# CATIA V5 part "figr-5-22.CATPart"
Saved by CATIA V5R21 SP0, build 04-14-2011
Part number: Part1
Bounding box of the stored display mesh (mm): x -50 to 50, y 0 to 90.129, z 0 to 181.346
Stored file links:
  D:\CATIA V5R21 E-RESOURCES\CATIA-V5R21\catia-v5r21-prt\c05-catia-v5r20-prt\catia-v5r21-figr-5-22.CATPart
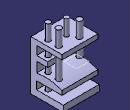
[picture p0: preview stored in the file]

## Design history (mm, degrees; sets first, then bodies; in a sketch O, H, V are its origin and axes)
Set1
  Plane1: type Offset, RefPlane face of Pad1, Offset 44, reversed
  Plane2: type Offset, RefPlane face of Pad1, Offset -46, reversed
Body1 (main body)
  Sketch1 on yz-plane, origin (0, 0, 0), H (0, 1, 0), V (0, 0, 1)
    line L1 (0, 0) -> (90.1292, 0)
    line L2 (90.1292, 0) -> (90.1292, 17.5473)
    line L3 (90.1292, 17.5473) -> (15.9521, 17.5473)
    line L4 (15.9521, 17.5473) -> (15.9521, 39.2532)
    line L5 (15.9521, 39.2532) -> (86.4281, 39.2532)
    line L6 (86.4281, 39.2532) -> (86.4281, 51.1017)
    arc A1 centre (39.4717, -66.63) radius 126.7503 from (86.4281, 51.1017) to (16.1896, 57.9637) ccw
    line L7 (16.1896, 57.9637) -> (16.1896, 86.2043)
    line L8 (16.1896, 86.2043) -> (46.6673, 86.2043)
    line L9 (46.6673, 86.2043) -> (46.6673, 100.2494)
    line L10 (46.6673, 100.2494) -> (16.1896, 100.2494)
    point P12 (16.1896, 100.2494)
    line L11 (16.1896, 100.2494) -> (16.1896, 124.3269)
    line L12 (16.1896, 124.3269) -> (86.4281, 124.3269)
    point P14 (86.4281, 124.3269)
    line L13 (86.4281, 124.3269) -> (86.4281, 137.3459)
    line L14 (86.4281, 137.3459) -> (0, 137.3459)
    point P16 (0, 137.3459)
    line L15 (0, 137.3459) -> (0, 0)
    horizontal: L1 H, L3 H, L5 H, L8 H, L10 H, L12 H, L14 H
    vertical: L2 V, L4 V, L6 V, L7 V, L9 V, L11 V, L13 V, L15 V
    coincidence: P12 L7, P14 L6, P16 V
  Pad1: profile Sketch1, direction (1, 0, 0), length 50, mirrored extent
  Sketch2 on Plane1, origin (0, 0, 181.3459), H (1, 0, 0), V (0, 1, 0)
    circle A1 centre (33.9095, 61.631) radius 7.5057
  Pad2: profile Sketch2, direction (0, 0, -1), up to face of Pad1
  Sketch3 on Plane1, origin (0, 0, 181.3459), H (1, 0, 0), V (0, -1, 0)
    circle A1 centre (-16.2674, -69.1948) radius 7.8522
  Pad3: profile Sketch3, direction (0, 0, -1), up to Plane2
  Sketch4 on Plane1, origin (0, 0, 181.3459), H (1, 0, 0), V (0, -1, 0)
    circle A1 centre (34.469, -32.4508) radius 7.1315
  Pad4: profile Sketch4, direction (0, 0, -1), up to the existing solid (limit type 3)
  Sketch5 on Plane1, origin (0, 0, 181.3459), H (1, 0, 0), V (0, -1, 0)
    circle A1 centre (-3.1833, -46.4863) radius 6.6131
  Pad5: profile Sketch5, direction (0, 0, -1), up to the existing solid (limit type 2)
